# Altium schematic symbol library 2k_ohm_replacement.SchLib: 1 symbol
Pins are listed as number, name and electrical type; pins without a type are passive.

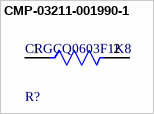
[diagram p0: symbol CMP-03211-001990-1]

## CMP-03211-001990-1
designator R?, comment CRGCQ0603F1K8
CRGCQ 0603 1K8 1%; Manufacturer: TE Connectivity; Power Rating: 0.1W; Temperature Coefficient: ±100ppm/°C; Resistance: 1.8KΩ; Tolerance: 0.01; Voltage Rating: 75V; Value: 1.8KΩ
footprint FP-CRGCQ0603-IPC_C
footprint FP-CRGCQ0603-IPC_B
footprint FP-CRGCQ0603-IPC_A
pins: 1, 2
